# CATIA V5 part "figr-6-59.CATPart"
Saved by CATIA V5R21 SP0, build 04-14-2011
Part number: Part1
Bounding box of the stored display mesh (mm): x -50.648 to 50.648, y -72.183 to 72.183, z -40 to 40
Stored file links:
  D:\CATIA V5R21 E-RESOURCES\CATIA-V5R21\catia-v5r21-prt\c06-catia-v5r21-prt\c06-catia-v5r21-figr-6-59.CATPart
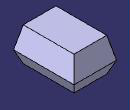
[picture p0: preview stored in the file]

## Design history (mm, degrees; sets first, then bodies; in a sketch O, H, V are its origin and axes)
Body1 (main body)
  Sketch1 on xy-plane, origin (0, 0, 0), H (1, 0, 0), V (0, 1, 0)
    line L1 (-50.6478, 72.1832) -> (50.6478, 72.1832)
    line L2 (50.6478, 72.1832) -> (50.6478, -72.1832)
    line L3 (50.6478, -72.1832) -> (-50.6478, -72.1832)
    line L4 (-50.6478, -72.1832) -> (-50.6478, 72.1832)
    axis line L5 (50.6478, -72.1832) -> (-50.6478, 72.1832)
    horizontal: L1 H, L3 H
    vertical: L2 V, L4 V
    midpoint: O L5
  Pad1: profile Sketch1, direction (0, 0, 1), length 40, mirrored extent
  Draft1: Angle 30, Neutral xy-plane, PullDir (0, 0, 1), SupportToDraft (face of Pad1; face of Pad1)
